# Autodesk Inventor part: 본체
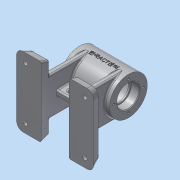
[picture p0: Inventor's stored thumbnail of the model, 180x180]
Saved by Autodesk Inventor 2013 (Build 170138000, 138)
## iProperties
Created: 2016-07
Part Number: 본체
Material: 알루미늄 6061
Document SubType Name: Modeling
Designer: dgall
Density: 1 g/cm^3
Author: dgall
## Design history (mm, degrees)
sketch "스케치1"
  geometry: L1 (-35, 0)-(35, 0); L2 (35, 0)-(35, 27); L3 (35, 27)-(-35, 27); L4 (-35, 27)-(-35, 0); L5 (-35, 16)-(-23.3, 16); L6 (-23, 15.7)-(-23, 14); L7 (-23, 14)-(-21, 14); L8 (-21, 14)-(-21, 22); L9 (-21, 22)-(21, 22); L10 (21, 22)-(21, 14); L11 (21, 14)-(23, 14); L12 (23, 14)-(23, 15.7); L13 (23.3, 16)-(35, 16); A1 r 0.3 centre (-23.3, 15.7) between (-23, 15.7) and (-23.3, 16); A2 r 0.3 centre (23.3, 15.7) between (23.3, 16) and (23, 15.7); 4 further points
  constraints: 26 end point, 6 point on line, 5 parallel, 4 perpendicular, 4 point on circle, 4 tangent, 2 centre point, 2 collinear, 2 vertical, 1 coincident, 1 equal radius, 1 horizontal, 1 midpoint
  dimensions: "d0" = 12 distance of L5.start point (-23, 16); "d2" = 42 distance of L8.end L9.end; "d3" = 12 distance of point (23, 16) L13.end; "d4" = 70 distance of L1.start L1.end; "d5" = 54 diameter of L3 L1; "d6" = 32 diameter of L5 L1; "d7" = 28 diameter of L7 L1; "d8" = 44 diameter of L9 L1; "d9" = 28 diameter of L11 L1; "d10" = 32 diameter of L13 L1; "d12" = 0.3 radius of A1
revolve "회전1" sketch "스케치1" stored, may be unused: angle "d11" = 90 deg
node "작업 평면1"
sketch "스케치2"
  geometry: L1 (-55, 50)-(-20, 50); L2 (-20, 50)-(-20, -50); L3 (-20, -50)-(-55, -50); L4 (-55, -50)-(-55, 50); 2 further points
  constraints: 8 end point, 2 parallel, 1 horizontal, 1 horizontal alignment, 1 midpoint, 1 perpendicular
  dimensions: "d14" = 35 distance between parallel lines of L2 L4; "d16" = 100 distance between parallel lines of L3 L1; "d17" = 55 distance from line of L4 point (0, 0)
extrude "돌출1" join sketch "스케치2" distance "d18" = 12; taper "d19" = 0 deg
sketch "스케치3"
  geometry: L1 (20, 50)-(20, -50) reference; L2 (20, 27)-(28, 27); L3 (28, 27)-(28, -27); L4 (28, -27)-(20, -27); L5 (20, -27)-(20, 27); 2 further points
  constraints: 8 end point, 2 parallel, 1 horizontal, 1 horizontal alignment, 1 midpoint, 1 perpendicular, 1 point on line
  dimensions: "d21" = 8 distance of L3.end L4.end; "d23" = 54 distance between parallel lines of L4 L2
extrude "돌출2" join sketch "스케치3" stored distance "d24" = 12; taper "d25" = 0 deg
fillet "모깎기9" dims "d111" = 10
feature "면 기울기2" dims angle "d26" = 20 deg
feature "면 기울기3" dims angle "d27" = 20 deg
sketch "스케치4"
  geometry: L1 (55, 40.603)-(55, -40.603) reference; 10 further points; 1 other entity
  constraints: 1 other
  dimensions: "d29" = 12.5 dimension on point (42.5, -37.5); "d30" = 12.5 distance from line of point (42.5, -37.5) L1
hole "구멍1" sketch "스케치4" at (42.5, -37.5) diameter "d31" = 6; stored, may be unused: countersink angle "d35" = 90 deg, drill point angle "d37" = 118 deg; dims "d32" = 6, "d33" = 10, "d34" = 4, "d36" = 8
sketch "스케치12"
  geometry: C1 r 16 at (0, 0) reference; 1 further point
  constraints: 1 vertical alignment
  dimensions: "d81" = 21 distance of C1.centre point (0, 21)
hole "구멍4" sketch "스케치12" at (0, 21) diameter "d82" = 3.242; stored, may be unused: countersink angle "d86" = 90 deg, drill point angle "d88" = 118 deg; dims "d83" = 8, "d84" = 10, "d85" = 4, "d87" = 10
sketch "스케치5"
  geometry: L1 (-19.942, -48)-(20.009, -48); L2 (-35, -27)-(35, -27) reference; 1 further point
  constraints: 2 end point, 1 horizontal
  dimensions: "d38" = 21 distance between parallel lines of L1 L2
feature "리브1" sketch "스케치5" dims "d39" = 1, "d40" = 8, "d41" = 0, "d42" = 0, "d43" = 1, "d44" = 1
sketch "스케치6"
  geometry: L1 (40, -21.298)-(0, -21.298) reference; L2 (12, -7.798)-(28, -7.798); L3 (28, -14.798)-(12, -14.798); L4 (20, -7.798)-(20, -14.976); L5 (65.603, -43.298)-(40, -43.298) reference; A1 r 3.5 centre (28, -11.298) between (28, -14.798) and (28, -7.798); A2 r 3.5 centre (12, -11.298) between (12, -7.798) and (12, -14.798); 3 further points
  constraints: 6 end point, 4 point on circle, 2 centre point, 2 parallel, 2 tangent, 1 equal radius, 1 midpoint, 1 perpendicular, 1 vertical alignment
  dimensions: "d45" = 3.5 radius of A1; "d47" = 23 dimension on A1 A2; "d49" = 11.5 dimension on A2 L4; "d50" = 32 distance from line of L5 A1.centre
extrude "돌출3" cut sketch "스케치6" stored distance "d51" = 12; taper "d52" = 0 deg
sketch "스케치7"
  geometry: L1 (0, 0)-(-12.358, 0); L2 (0, 0)-(-25.441, -15.898)
  constraints: 4 end point, 1 horizontal
  dimensions: "d53" = 30 distance of L1.start L2.end; "d55" = 32 deg angle of L2 L1
node "작업 평면2"
sketch "스케치8"
  geometry: C1 r 6 at (0, 0); 1 further point
  constraints: 1 centre point, 1 coincident
  dimensions: "d56" = 12 diameter of C1
extrude "돌출4" join sketch "스케치8" stored distance "d58" = 12; taper "d59" = 0 deg
sketch "스케치9"
  geometry: 1 further point
hole "구멍2" sketch "스케치9" at (0, 0) diameter "d60" = 5.188; stored, may be unused: countersink angle "d64" = 90 deg, drill point angle "d66" = 118 deg; dims "d61" = 6, "d62" = 10, "d63" = 4, "d65" = 13
node "작업 평면3"
sketch "스케치11"
  geometry: L1 (-35, 27)-(-35, -27) reference; L2 (35, 27)-(35, -27) reference; C1 r 5 at (13, 0); 1 further point
  constraints: 1 centre point, 1 horizontal alignment
  dimensions: "d69" = 10 diameter of C1; "d97" = 22 distance from line of L2 C1.centre
extrude "돌출5" join sketch "스케치11" stored distance "d70" = 12; taper "d71" = 0 deg
hole "구멍3" diameter "d74" = 5.188; stored, may be unused: countersink angle "d78" = 90 deg, drill point angle "d80" = 118 deg; dims "d72" = 10, "d73" = 10, "d75" = 6, "d76" = 10, "d77" = 4, "d79" = 18
node "작업 평면4"
sketch "스케치13"
  geometry: L1 (-35, -27)-(-35, 27) reference; L2 (-35, 27)-(35, 27) reference; 2 further points
  constraints: 1 other
  dimensions: "d93" = 35 distance from line of point (0, 0) L1; "d94" = 27 distance from line of point (0, 0) L2
feature "엠보싱1" sketch "스케치13" dims "d0" = 12, "d2" = 42, "d3" = 12, "d4" = 70, "d5" = 54, "d6" = 32, "d7" = 28, "d8" = 44, "d9" = 28, "d10" = 32, "d12" = 0.3, "d95" = 0.5, "d96" = 0
fillet "모깎기2" dims "d98" = 2
fillet "모깎기3" dims "d99" = 2
fillet "모깎기4" dims "d100" = 2
fillet "모깎기5" dims "d101" = 2
chamfer "모따기1" distance "d102" = 1; stored, may be unused: second distance "d103" = 2, angle "d104" = 45 deg
chamfer "모따기2" distance "d105" = 1; stored, may be unused: second distance "d106" = 2, angle "d107" = 45 deg
fillet "모깎기6" dims "d108" = 2
fillet "모깎기7" dims "d109" = 2
node "솔리드1"
mirror "대칭1"
pattern_circular "원형 패턴1" dims angle "d90" = 360 deg
mirror "대칭2"
other parameters: "d92" = 43
